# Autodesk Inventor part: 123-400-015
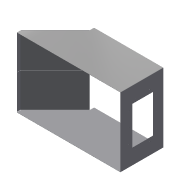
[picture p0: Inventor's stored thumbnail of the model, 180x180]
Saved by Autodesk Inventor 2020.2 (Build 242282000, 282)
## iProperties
Created: 2006-08
Part Number: 123-400-015
Material: Stal
Document SubType Name: Sheet Metal
Designer: F.Stasiak
Description: Osłona
Density: 7.85 g/cm^3
Sheet Metal Rule: Domyślny_mm
Appearance: Domyślna
Mass: 54357.4 g
Surface Area: 55716.3 cm^2
Volume: 6924.51 cm^3
Flat Pattern Width: 91.1188 cm
Flat Pattern Length: 479.368 cm
Flat Pattern Area: 43679.4 cm^2
Sheet Metal Width: 911,188 mm
Sheet Metal Length: 4793,679 mm
Sheet Metal Area: 4367943,194 mm^2
Manager: www.cadconsulting.pl
Company: Fabian Stasiak CAD Consulting
Author: F.Stasiak
Subject: Zbiór ćwiczeń. Autodesk Inventor 2020. Kurs podstawowy
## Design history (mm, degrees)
node "Powierzchnia1"
  sketch "Szkic1"
    geometry: L1 (-738, -12)-(738, -12) reference; L2 (750, 48)-(750, 548) reference; L3 (-238, 608)-(738, 608) reference; L4 (-750, 48)-(-250, 548) reference; L5 (-750, 48)-(-750, -12); L6 (-750, -12)-(-738, -12); L7 (-250, 548)-(-250, 608); L8 (-250, 608)-(-238, 608); L9 (750, 548)-(750, 608); L10 (750, 608)-(738, 608); L11 (750, 48)-(750, -12); L12 (750, -12)-(738, -12)
    constraints: 16 end point, 7 perpendicular, 1 collinear, 1 point on line
node "Płaszczyzna konstrukcyjna1"
node "Powierzchnia2"
  sketch "Szkic2"
    geometry: L1 (750, -12)-(-750, -12) reference; L2 (750, 48)-(750, -12) reference; L3 (250, 548)-(750, 48) reference; L4 (250, 608)-(250, 548) reference; L5 (-750, 608)-(250, 608) reference; L6 (-750, -12)-(-750, 608) reference
feature "Gięcie2" dims "d6" = 2.5 (= SzerokośćGięciaPodcięcia), "d7" = 1.25 (= GłębokośćGięciaPodcięcia), "d8" = 5 (= MinimalnaPozostałość), "d9" = 2.5 (= PromieńGięcia), "d10" = 2.5 (= PromieńGięcia), "d40" = 2.5 (= Grubość), "SeamGap" = 0.01
node "Kołnierz1"
node "Kołnierz2"
node "Kołnierz3"
node "Kołnierz4"
feature "Zaokrąglenie narożnika1" dims "d39" = 10
sketch "Szkic7"
  geometry: L1 (-771, 471.129)-(-221, 471.129); L2 (-221, 471.129)-(-221, 171.129); L3 (-221, 171.129)-(-771, 171.129); L4 (-771, 171.129)-(-771, 471.129); L5 (-496, 560)-(-496, 60.732) reference; L6 (-771, 471.129)-(-221, 171.129); L7 (-221, 471.129)-(-771, 171.129); 2 further points
  constraints: 12 end point, 2 midpoint, 2 parallel, 1 horizontal, 1 perpendicular, 1 point on line
  dimensions: "d41" = 550 distance of L2.end L3.end; "d42" = 300 distance of L1.end L2.end
feature "Wytnij1" sketch "Szkic7" dims "d43" = 2.5 (= Grubość), "d44" = 0
node "Otwory1"
node "Bryła1"
node "Korpusy bryłowe"
node "Korpusy powierzchniowe"
node "Odniesienie1"
node "Odniesienie2"
node "Odniesienie3"
node "Odniesienie4"
feature "Płyta1" dims "d40" = 2.5 (= Grubość)
node "Pętla rzutowana1"
feature "Płyta2" dims "d1" = 2.5 (= PromieńGięcia), "d2" = 2.5 (= SzerokośćGięciaPodcięcia), "d4" = 5 (= MinimalnaPozostałość), "d40" = 2.5 (= Grubość)
feature "Gięcie1" dims "d1" = 2.5 (= PromieńGięcia), "d2" = 2.5 (= SzerokośćGięciaPodcięcia), "d3" = 1.25 (= GłębokośćGięciaPodcięcia), "d4" = 5 (= MinimalnaPozostałość), "d5" = 2.5 (= PromieńGięcia), "d40" = 2.5 (= Grubość), "SeamGap" = 0.01
sketch "Szkic3"
  geometry: L1 (-2.5, 0)-(-707.107, 0); L2 (-707.107, 0)-(-707.107, 501); L3 (-707.107, 501)-(-2.5, 501); L4 (-2.5, 501)-(-2.5, 0)
  constraints: 8 end point
feature "Płyta3" dims "d11" = 2.5 (= SzerokośćGięciaPodcięcia), "d13" = 5 (= MinimalnaPozostałość), "d15" = 501, "d16" = 90 deg, "d17" = 2.5 (= PromieńGięcia), "d40" = 2.5 (= Grubość)
feature "Gięcie3" dims "d11" = 2.5 (= SzerokośćGięciaPodcięcia), "d12" = 1.25 (= GłębokośćGięciaPodcięcia), "d13" = 5 (= MinimalnaPozostałość), "d14" = 2.5 (= PromieńGięcia), "d15" = 501, "d16" = 90 deg, "d17" = 2.5 (= PromieńGięcia), "d40" = 2.5 (= Grubość), "SeamGap" = 0.01
sketch "Szkic4"
  geometry: L1 (704.607, 0)-(704.607, -501); L2 (704.607, -501)-(0, -501); 1 other entity
  constraints: 4 end point, 4 other
feature "Płyta4" dims "d18" = 2.5 (= SzerokośćGięciaPodcięcia), "d20" = 5 (= MinimalnaPozostałość), "d22" = 501, "d23" = 90 deg, "d24" = 2.5 (= PromieńGięcia), "d40" = 2.5 (= Grubość)
feature "Gięcie4" dims "d18" = 2.5 (= SzerokośćGięciaPodcięcia), "d19" = 1.25 (= GłębokośćGięciaPodcięcia), "d20" = 5 (= MinimalnaPozostałość), "d21" = 2.5 (= PromieńGięcia), "d22" = 501, "d23" = 90 deg, "d24" = 2.5 (= PromieńGięcia), "d40" = 2.5 (= Grubość), "SeamGap" = 0.01
sketch "Szkic5"
  geometry: L1 (0, -496)-(57.879, -496); L2 (57.879, -496)-(57.879, 0); 1 other entity
  constraints: 4 end point, 4 other
feature "Płyta5" dims "d25" = 2.5 (= SzerokośćGięciaPodcięcia), "d27" = 5 (= MinimalnaPozostałość), "d29" = 57.87868, "d30" = -45 deg, "d31" = 2.5 (= PromieńGięcia), "d40" = 2.5 (= Grubość)
feature "Gięcie5" dims "d25" = 2.5 (= SzerokośćGięciaPodcięcia), "d26" = 1.25 (= GłębokośćGięciaPodcięcia), "d27" = 5 (= MinimalnaPozostałość), "d28" = 2.5 (= PromieńGięcia), "d29" = 57.87868, "d30" = -45 deg, "d31" = 2.5 (= PromieńGięcia), "d40" = 2.5 (= Grubość), "SeamGap" = 0.01
sketch "Szkic6"
  geometry: L1 (0, -496)-(57.879, -496); L2 (57.879, -496)-(57.879, 0); 1 other entity
  constraints: 4 end point, 4 other
feature "Płyta6" dims "d32" = 2.5 (= SzerokośćGięciaPodcięcia), "d34" = 5 (= MinimalnaPozostałość), "d36" = 57.87868, "d37" = -45 deg, "d38" = 2.5 (= PromieńGięcia), "d40" = 2.5 (= Grubość)
feature "Gięcie6" dims "d32" = 2.5 (= SzerokośćGięciaPodcięcia), "d33" = 1.25 (= GłębokośćGięciaPodcięcia), "d34" = 5 (= MinimalnaPozostałość), "d35" = 2.5 (= PromieńGięcia), "d36" = 57.87868, "d37" = -45 deg, "d38" = 2.5 (= PromieńGięcia), "d40" = 2.5 (= Grubość), "SeamGap" = 0.01
node "PłaskiWzór"
sketch "Szkic8"
  geometry: 10 further points
hole "Otwór1" sketch "Szkic8" diameter "d45" = 6.647; stored, may be unused: countersink angle "d49" = 90 deg, drill point angle "d51" = 0 deg; dims "d46" = 6, "d47" = 4, "d48" = 2, "d50" = 8
feature "Definicja2" dims "d0" = 2.5 (derived)
other parameters: "Grubość" = 2.5 (derived), "PromieńGięcia" = 2.5 (= Grubość), "SzerokośćGięciaPodcięcia" = 2.5 (= Grubość), "GłębokośćGięciaPodcięcia" = 1.25 (= 0.5 x Grubość), "MinimalnaPozostałość" = 5 (= 2 x Grubość), "PromieńPrzejścia" = 2.5 (= PromieńGięcia), "d0" = 2.5 (= PromieńGięcia), "Rozmiar_promienia_Jacobiego" = 2.5 (= PromieńGięcia), "Wielk_odstępu" = 2.5 (= Grubość), "Grubość" = 2.5, "GłębokośćGięciaPodcięcia" = 1.25, "MinimalnaPozostałość" = 5, "PromieńGięcia" = 2.5, "PromieńPrzejścia" = 2.5, "Rozmiar_promienia_Jacobiego" = 2.5, "SzerokośćGięciaPodcięcia" = 2.5, "Wielk_odstępu" = 2.5
